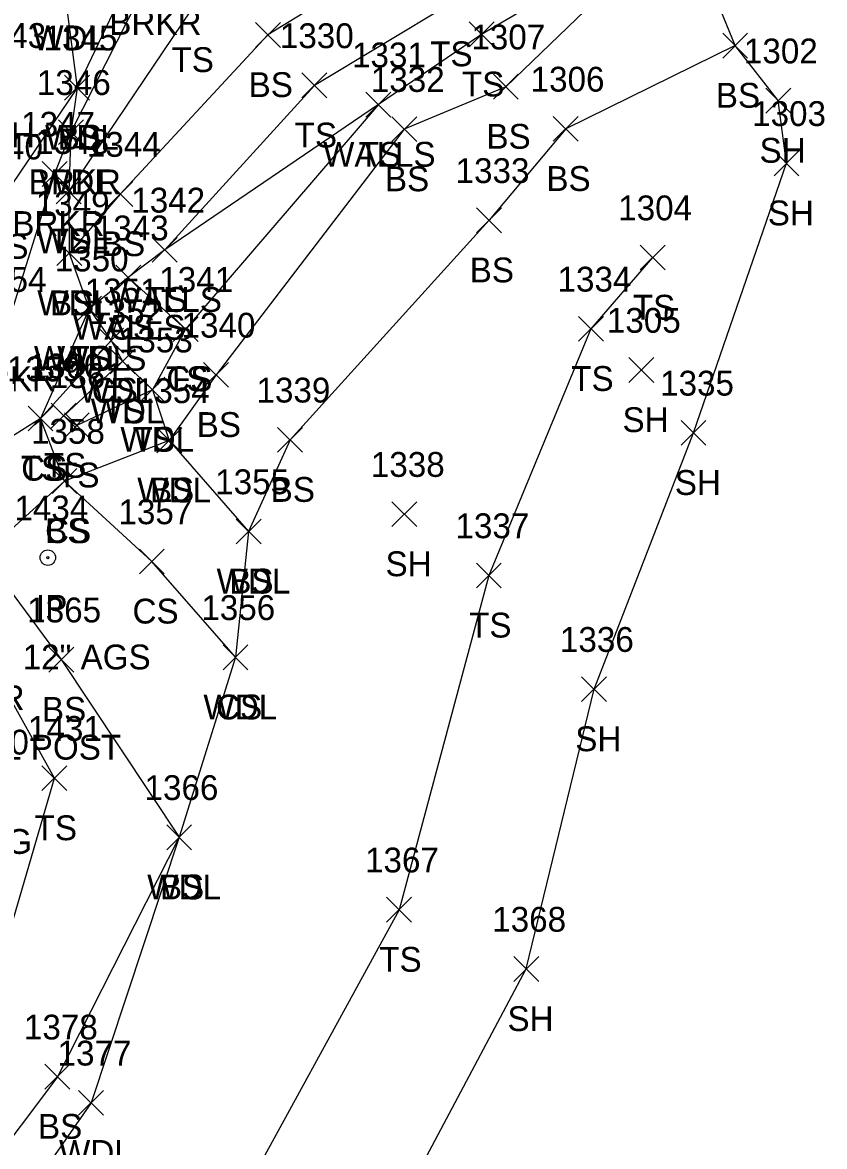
# Model space of a CAD drawing. Extents: x 1441651 to 1442140, y 243798 to 245625.
# Drawn here: x 1442075.5 to 1442140.1, y 245354.1 to 245444.6 of the extents above; entities that cross this region are included whole.
import ezdxf

# ---------------------------------------------------------------- set-up
doc = ezdxf.new("R2010")
doc.units = 0
for name, color, linetype in [('L_A', 7, 'Continuous'), ('L_I', 7, 'Continuous'), ('L_TIC', 7, 'Continuous'), ('LAWA', 7, 'Continuous'), ('LAWE', 7, 'Continuous'), ('LELB', 7, 'Continuous'), ('LSOGP', 7, 'Continuous'), ('LWS', 7, 'Continuous'), ('M_A', 7, 'Continuous'), ('M_C', 7, 'Continuous'), ('M_I', 7, 'Continuous'), ('MPIR', 7, 'Continuous'), ('P_A', 7, 'Continuous'), ('P_I', 7, 'Continuous'), ('R_A', 7, 'Continuous'), ('R_C', 7, 'Continuous')]:
    doc.layers.add(name, color=color, linetype=linetype)

msp = doc.modelspace()

# ---------------------------------------------------------------- linework, layer by layer
at = {"layer": 'L_TIC'}
for points in [[(1442094.312, 245442.627), (1442096.312, 245444.627)], [(1442096.312, 245442.627), (1442094.312, 245444.627)], [(1442111.528, 245442.672), (1442113.528, 245444.672)], [(1442113.528, 245442.672), (1442111.528, 245444.672)], [(1442131.95, 245441.769), (1442133.95, 245443.769)], [(1442133.95, 245441.769), (1442131.95, 245443.769)], [(1442098.053, 245438.565), (1442100.053, 245440.565)], [(1442100.053, 245438.565), (1442098.053, 245440.565)], [(1442078.931, 245438.38), (1442080.931, 245440.38)], [(1442080.931, 245438.38), (1442078.931, 245440.38)], [(1442078.931, 245438.38), (1442080.931, 245440.38)], [(1442080.931, 245438.38), (1442078.931, 245440.38)], [(1442113.47, 245438.461), (1442115.47, 245440.461)], [(1442115.47, 245438.461), (1442113.47, 245440.461)], [(1442103.209, 245437.017), (1442105.209, 245439.017)], [(1442105.209, 245437.017), (1442103.209, 245439.017)], [(1442103.209, 245437.017), (1442105.209, 245439.017)], [(1442105.209, 245437.017), (1442103.209, 245439.017)], [(1442135.427, 245437.337), (1442137.427, 245439.337)], [(1442137.427, 245437.337), (1442135.427, 245439.337)], [(1442105.293, 245435.041), (1442107.293, 245437.041)], [(1442107.293, 245435.041), (1442105.293, 245437.041)], [(1442118.3, 245435.064), (1442120.3, 245437.064)], [(1442120.3, 245435.064), (1442118.3, 245437.064)], [(1442078.446, 245434.792), (1442080.446, 245436.792)], [(1442080.446, 245434.792), (1442078.446, 245436.792)], [(1442078.446, 245434.792), (1442080.446, 245436.792)], [(1442080.446, 245434.792), (1442078.446, 245436.792)], [(1442136.088, 245432.293), (1442138.088, 245434.293)], [(1442138.088, 245432.293), (1442136.088, 245434.293)], [(1442077.126, 245431.436), (1442079.126, 245433.436)], [(1442079.126, 245431.436), (1442077.126, 245433.436)], [(1442078.259, 245430.039), (1442080.259, 245432.039)], [(1442080.259, 245430.039), (1442078.259, 245432.039)], [(1442078.259, 245430.039), (1442080.259, 245432.039)], [(1442080.259, 245430.039), (1442078.259, 245432.039)], [(1442082.416, 245429.813), (1442084.416, 245431.813)], [(1442084.416, 245429.813), (1442082.416, 245431.813)], [(1442112.122, 245427.701), (1442114.122, 245429.701)], [(1442114.122, 245427.701), (1442112.122, 245429.701)], [(1442078.309, 245425.048), (1442080.309, 245427.048)], [(1442080.309, 245425.048), (1442078.309, 245427.048)], [(1442078.309, 245425.048), (1442080.309, 245427.048)], [(1442080.309, 245425.048), (1442078.309, 245427.048)], [(1442085.997, 245425.322), (1442087.997, 245427.322)], [(1442087.997, 245425.322), (1442085.997, 245427.322)], [(1442085.997, 245425.322), (1442087.997, 245427.322)], [(1442087.997, 245425.322), (1442085.997, 245427.322)], [(1442125.299, 245424.698), (1442127.299, 245426.698)], [(1442127.299, 245424.698), (1442125.299, 245426.698)], [(1442083.06, 245423.085), (1442085.06, 245425.085)], [(1442085.06, 245423.085), (1442083.06, 245425.085)], [(1442083.06, 245423.085), (1442085.06, 245425.085)], [(1442085.06, 245423.085), (1442083.06, 245425.085)], [(1442079.914, 245420.582), (1442081.914, 245422.582)], [(1442081.914, 245420.582), (1442079.914, 245422.582)], [(1442079.914, 245420.582), (1442081.914, 245422.582)], [(1442081.914, 245420.582), (1442079.914, 245422.582)], [(1442079.914, 245420.582), (1442081.914, 245422.582)], [(1442081.914, 245420.582), (1442079.914, 245422.582)], [(1442087.683, 245418.936), (1442089.683, 245420.936)], [(1442089.683, 245418.936), (1442087.683, 245420.936)], [(1442087.683, 245418.936), (1442089.683, 245420.936)], [(1442089.683, 245418.936), (1442087.683, 245420.936)], [(1442120.335, 245418.958), (1442122.335, 245420.958)], [(1442122.335, 245418.958), (1442120.335, 245420.958)], [(1442081.678, 245418.008), (1442083.678, 245420.008)], [(1442083.678, 245418.008), (1442081.678, 245420.008)], [(1442081.678, 245418.008), (1442083.678, 245420.008)], [(1442083.678, 245418.008), (1442081.678, 245420.008)], [(1442082.608, 245416.345), (1442084.608, 245418.345)], [(1442084.608, 245416.345), (1442082.608, 245418.345)], [(1442082.608, 245416.345), (1442084.608, 245418.345)], [(1442084.608, 245416.345), (1442082.608, 245418.345)], [(1442090.133, 245415.249), (1442092.133, 245417.249)], [(1442092.133, 245415.249), (1442090.133, 245417.249)], [(1442124.388, 245415.642), (1442126.388, 245417.642)], [(1442126.388, 245415.642), (1442124.388, 245417.642)], [(1442084.999, 245414.059), (1442086.999, 245416.059)], [(1442086.999, 245414.059), (1442084.999, 245416.059)], [(1442084.999, 245414.059), (1442086.999, 245416.059)], [(1442086.999, 245414.059), (1442084.999, 245416.059)], [(1442075.992, 245411.732), (1442077.992, 245413.732)], [(1442077.992, 245411.732), (1442075.992, 245413.732)], [(1442075.992, 245411.732), (1442077.992, 245413.732)], [(1442077.992, 245411.732), (1442075.992, 245413.732)], [(1442075.992, 245411.732), (1442077.992, 245413.732)], [(1442077.992, 245411.732), (1442075.992, 245413.732)], [(1442077.858, 245411.961), (1442079.858, 245413.961)], [(1442079.858, 245411.961), (1442077.858, 245413.961)], [(1442078.917, 245411.184), (1442080.917, 245413.184)], [(1442080.917, 245411.184), (1442078.917, 245413.184)], [(1442078.917, 245411.184), (1442080.917, 245413.184)], [(1442080.917, 245411.184), (1442078.917, 245413.184)], [(1442128.596, 245410.581), (1442130.596, 245412.581)], [(1442130.596, 245410.581), (1442128.596, 245412.581)], [(1442086.362, 245409.975), (1442088.362, 245411.975)], [(1442088.362, 245409.975), (1442086.362, 245411.975)], [(1442086.362, 245409.975), (1442088.362, 245411.975)], [(1442088.362, 245409.975), (1442086.362, 245411.975)], [(1442096.091, 245410.023), (1442098.091, 245412.023)], [(1442098.091, 245410.023), (1442096.091, 245412.023)], [(1442077.918, 245406.703), (1442079.918, 245408.703)], [(1442079.918, 245406.703), (1442077.918, 245408.703)], [(1442077.918, 245406.703), (1442079.918, 245408.703)], [(1442079.918, 245406.703), (1442077.918, 245408.703)], [(1442105.295, 245404.036), (1442107.295, 245406.036)], [(1442107.295, 245404.036), (1442105.295, 245406.036)], [(1442092.756, 245402.639), (1442094.756, 245404.639)], [(1442094.756, 245402.639), (1442092.756, 245404.639)], [(1442092.756, 245402.639), (1442094.756, 245404.639)], [(1442094.756, 245402.639), (1442092.756, 245404.639)], [(1442084.96, 245400.224), (1442086.96, 245402.224)], [(1442086.96, 245400.224), (1442084.96, 245402.224)], [(1442112.11, 245399.096), (1442114.11, 245401.096)], [(1442114.11, 245399.096), (1442112.11, 245401.096)], [(1442091.693, 245392.503), (1442093.693, 245394.503)], [(1442093.693, 245392.503), (1442091.693, 245394.503)], [(1442091.693, 245392.503), (1442093.693, 245394.503)], [(1442093.693, 245392.503), (1442091.693, 245394.503)], [(1442077.662, 245392.315), (1442079.662, 245394.315)], [(1442079.662, 245392.315), (1442077.662, 245394.315)], [(1442120.582, 245389.94), (1442122.582, 245391.94)], [(1442122.582, 245389.94), (1442120.582, 245391.94)], [(1442077.106, 245382.773), (1442079.106, 245384.773)], [(1442079.106, 245382.773), (1442077.106, 245384.773)], [(1442087.165, 245378.007), (1442089.165, 245380.007)], [(1442089.165, 245378.007), (1442087.165, 245380.007)], [(1442087.165, 245378.007), (1442089.165, 245380.007)], [(1442089.165, 245378.007), (1442087.165, 245380.007)], [(1442104.872, 245372.176), (1442106.872, 245374.176)], [(1442106.872, 245372.176), (1442104.872, 245374.176)], [(1442115.121, 245367.402), (1442117.121, 245369.402)], [(1442117.121, 245367.402), (1442115.121, 245369.402)], [(1442077.347, 245358.722), (1442079.347, 245360.722)], [(1442079.347, 245358.722), (1442077.347, 245360.722)], [(1442080.06, 245356.624), (1442082.06, 245358.624)], [(1442082.06, 245356.624), (1442080.06, 245358.624)]]:
    msp.add_lwpolyline(points, dxfattribs=at)
at = {"layer": 'LAWA'}
msp.add_lwpolyline([(1442094.004, 245495.984), (1442085.8, 245486.892), (1442079.595, 245477.001), (1442071.155, 245464.784), (1442068.683, 245457.119), (1442071.044, 245454.669), (1442072.716, 245452.8), (1442077.346, 245452.135), (1442078.907, 245447.391), (1442079.931, 245439.38), (1442079.446, 245435.792), (1442079.259, 245431.039), (1442079.309, 245426.048), (1442080.914, 245421.582), (1442082.678, 245419.008), (1442083.608, 245417.345), (1442085.999, 245415.059), (1442087.362, 245410.975), (1442093.756, 245403.639), (1442092.693, 245393.503), (1442088.165, 245379.007), (1442081.06, 245357.624), (1442070.182, 245342.029)], dxfattribs=at)
at = {"layer": 'LAWE'}
msp.add_lwpolyline([(1442108.799, 245476.467), (1442096.827, 245461.697), (1442085.936, 245448.636), (1442079.446, 245435.792), (1442078.126, 245432.436), (1442074.215, 245419.929), (1442069.905, 245412.33), (1442066.174, 245406.441), (1442060.085, 245400.813), (1442053.875, 245394.968), (1442048.801, 245389.024), (1442033.753, 245369.5), (1442027.295, 245353.918), (1442016.143, 245332.931), (1442008.363, 245317.18), (1442000.261, 245295.499)], dxfattribs=at)
at = {"layer": 'LELB'}
for points in [[(1442107.479, 245478.045), (1442095.111, 245463.136), (1442085.124, 245450.231), (1442079.931, 245439.38), (1442074.016, 245430.6), (1442072.192, 245422.421), (1442067.602, 245415.77), (1442063.525, 245410.875), (1442058.938, 245403.451), (1442051.468, 245396.66), (1442047.361, 245390.552), (1442031.625, 245371.637), (1442024.894, 245355.937), (1442013.328, 245334.791), (1442005.478, 245318.663), (1441997.832, 245296.612)], [(1442110.371, 245473.904), (1442098.105, 245459.473), (1442089.13, 245445.639), (1442079.259, 245431.039)], [(1442122.519, 245456.753), (1442106.231, 245450.329), (1442095.312, 245443.627), (1442083.416, 245430.813), (1442079.309, 245426.048)], [(1442128.7, 245453.168), (1442114.47, 245439.461), (1442106.293, 245436.041), (1442091.133, 245416.249), (1442087.362, 245410.975), (1442078.918, 245407.703), (1442072.375, 245401.791), (1442078.662, 245393.315), (1442088.165, 245379.007), (1442078.347, 245359.722), (1442066.466, 245343.929), (1442051.618, 245313.899)], [(1442128.7, 245453.168), (1442112.528, 245443.672), (1442104.209, 245438.017), (1442088.683, 245419.936), (1442085.999, 245415.059), (1442079.917, 245412.184)], [(1442128.7, 245453.168), (1442109.973, 245446.107), (1442099.053, 245439.565), (1442086.997, 245426.322)], [(1442132.95, 245442.769), (1442119.3, 245436.064), (1442113.122, 245428.701), (1442097.091, 245411.023), (1442093.756, 245403.639)], [(1442126.299, 245425.698), (1442121.335, 245419.958), (1442113.11, 245400.096), (1442105.872, 245373.176), (1442091.625, 245347.116), (1442084.744, 245336.784), (1442070.953, 245307.446)], [(1442088.683, 245419.936), (1442084.06, 245424.085), (1442082.678, 245419.008), (1442076.992, 245412.732)], [(1442080.914, 245421.582), (1442076.992, 245412.732), (1442069.82, 245408.225)], [(1442083.608, 245417.345), (1442078.858, 245412.961), (1442079.917, 245412.184)], [(1442092.693, 245393.503), (1442085.96, 245401.224), (1442078.918, 245407.703), (1442076.992, 245412.732)], [(1442066.466, 245343.929), (1442078.106, 245383.773), (1442072.276, 245394.261)]]:
    msp.add_lwpolyline(points, dxfattribs=at)
at = {"layer": 'LSOGP'}
msp.add_lwpolyline([(1442101.45, 245340.824), (1442116.121, 245368.402), (1442121.582, 245390.94), (1442129.596, 245411.581), (1442137.088, 245433.293), (1442136.427, 245438.337), (1442132.95, 245442.769), (1442128.7, 245453.168), (1442122.519, 245456.753), (1442110.371, 245473.904), (1442108.799, 245476.467), (1442107.479, 245478.045), (1442106.124, 245480.602), (1442104.092, 245484.162), (1442102.458, 245487.565), (1442099.331, 245492.7), (1442094.004, 245495.984), (1442092.912, 245497.466), (1442087.101, 245508.937)], dxfattribs=at)
at = {"layer": 'LWS'}
msp.add_lwpolyline([(1442104.209, 245438.017), (1442086.997, 245426.322), (1442084.06, 245424.085), (1442080.914, 245421.582)], dxfattribs=at)
at = {"layer": 'MPIR'}
for radius in [0.625, 0.0833]:
    msp.add_circle((1442077.58, 245401.531), radius, dxfattribs=at)

# ---------------------------------------------------------------- texts
at = {"layer": 'L_A'}
for s, p in [('BRKR', (1442082.527, 245443.636)), ('WDL', (1442076.325, 245442.391)), ('TS', (1442087.539, 245440.639)), ('TS', (1442108.382, 245441.107)), ('BS', (1442093.753, 245438.627)), ('TS', (1442110.937, 245438.672)), ('BS', (1442131.391, 245437.769)), ('CH', (1442072.676, 245434.58)), ('WDL', (1442077.349, 245434.38)), ('BS', (1442078.372, 245434.38)), ('TS', (1442097.462, 245434.565)), ('BS', (1442112.911, 245434.461)), ('SH', (1442134.915, 245433.337)), ('WALLS', (1442099.752, 245433.017)), ('TS', (1442102.619, 245433.017)), ('BRKR', (1442076.036, 245430.792)), ('WDL', (1442076.863, 245430.792)), ('BS', (1442104.734, 245431.041)), ('BS', (1442117.741, 245431.064)), ('SH', (1442135.576, 245428.293)), ('BRKR', (1442074.717, 245427.436)), ('WDL', (1442076.676, 245426.039)), ('TS', (1442077.668, 245426.039)), ('BS', (1442081.857, 245425.813)), ('BS', (1442072.457, 245425.6)), ('BS', (1442111.563, 245423.701)), ('WALLS', (1442082.54, 245421.322)), ('TS', (1442085.406, 245421.322)), ('WDL', (1442076.727, 245421.048)), ('BS', (1442077.75, 245421.048)), ('TS', (1442124.709, 245420.698)), ('WALLS', (1442079.603, 245419.085)), ('CS', (1442082.501, 245419.085)), ('WALLS', (1442076.457, 245416.582)), ('WDL', (1442078.331, 245416.582)), ('TS', (1442079.324, 245416.582)), ('TS', (1442087.092, 245414.936)), ('CS', (1442087.124, 245414.936)), ('TS', (1442119.745, 245414.958)), ('BRKR', (1442070.806, 245414.929)), ('WDL', (1442080.095, 245414.008)), ('CS', (1442081.119, 245414.008)), ('WDL', (1442081.025, 245412.345)), ('TS', (1442082.017, 245412.345)), ('SH', (1442123.876, 245411.642)), ('BS', (1442089.574, 245411.249)), ('WDL', (1442083.416, 245410.059)), ('TS', (1442084.408, 245410.059)), ('TS', (1442075.402, 245407.732)), ('CS', (1442075.433, 245407.732)), ('CS', (1442075.433, 245407.732)), ('TS', (1442077.267, 245407.961)), ('TS', (1442078.326, 245407.184)), ('TS', (1442078.326, 245407.184)), ('WDL', (1442084.78, 245405.975)), ('BS', (1442085.803, 245405.975)), ('BS', (1442095.532, 245406.023)), ('SH', (1442128.084, 245406.581)), ('CS', (1442077.359, 245402.703)), ('BS', (1442077.359, 245402.703)), ('SH', (1442104.783, 245400.036)), ('WDL', (1442091.174, 245398.639)), ('BS', (1442092.197, 245398.639)), ('CS', (1442084.401, 245396.224)), ('TS', (1442111.519, 245395.096)), ('BS', (1442077.103, 245388.315)), ('WDL', (1442090.111, 245388.503)), ('CS', (1442091.134, 245388.503)), ('SH', (1442120.07, 245385.94)), ('TS', (1442076.516, 245378.773)), ('WDL', (1442085.583, 245374.007)), ('BS', (1442086.606, 245374.007)), ('TS', (1442104.281, 245368.176)), ('SH', (1442114.609, 245363.402)), ('BS', (1442076.788, 245354.722)), ('WDL', (1442078.477, 245352.624))]:
    msp.add_text(s, height=2, dxfattribs=at).set_placement(p)
at = {"layer": 'L_I'}
for s, p in [('1443', (1442071.495, 245442.58)), ('1345', (1442077.238, 245442.38)), ('1345', (1442077.238, 245442.38)), ('1330', (1442096.274, 245442.565)), ('1307', (1442111.699, 245442.461)), ('1302', (1442133.655, 245441.337)), ('1331', (1442102.083, 245441.017)), ('1331', (1442102.083, 245441.017)), ('1346', (1442076.698, 245438.792)), ('1346', (1442076.698, 245438.792)), ('1332', (1442103.6, 245439.041)), ('1306', (1442116.473, 245439.064)), ('1303', (1442134.316, 245436.293)), ('1347', (1442075.433, 245435.436)), ('1348', (1442076.566, 245434.039)), ('1348', (1442076.566, 245434.039)), ('1440', (1442071.236, 245433.6)), ('1344', (1442080.723, 245433.813)), ('1333', (1442110.429, 245431.701)), ('1349', (1442076.608, 245429.048)), ('1349', (1442076.608, 245429.048)), ('1342', (1442084.304, 245429.322)), ('1342', (1442084.304, 245429.322)), ('1304', (1442123.528, 245428.698)), ('1343', (1442081.367, 245427.085)), ('1343', (1442081.367, 245427.085)), ('1350', (1442078.135, 245424.582)), ('1350', (1442078.135, 245424.582)), ('1350', (1442078.135, 245424.582)), ('1454', (1442071.522, 245422.929)), ('1341', (1442086.557, 245422.936)), ('1341', (1442086.557, 245422.936)), ('1334', (1442118.642, 245422.958)), ('1351', (1442080.552, 245422.008)), ('1351', (1442080.552, 245422.008)), ('1352', (1442080.915, 245420.345)), ('1352', (1442080.915, 245420.345)), ('1305', (1442122.616, 245419.642)), ('1340', (1442088.354, 245419.249)), ('1353', (1442083.306, 245418.059)), ('1353', (1442083.306, 245418.059)), ('1360', (1442076.031, 245415.961)), ('1359', (1442074.291, 245415.732)), ('1359', (1442074.291, 245415.732)), ('1359', (1442074.291, 245415.732)), ('1361', (1442077.743, 245415.184)), ('1361', (1442077.743, 245415.184)), ('1335', (1442126.903, 245414.581)), ('1354', (1442084.67, 245413.975)), ('1354', (1442084.67, 245413.975)), ('1339', (1442094.39, 245414.023)), ('1358', (1442076.225, 245410.703)), ('1358', (1442076.225, 245410.703)), ('1338', (1442103.602, 245408.036)), ('1355', (1442091.063, 245406.639)), ('1355', (1442091.063, 245406.639)), ('1357', (1442083.267, 245404.224)), ('1337', (1442110.417, 245403.096)), ('1365', (1442075.922, 245396.315)), ('1356', (1442089.945, 245396.503)), ('1356', (1442089.945, 245396.503)), ('1336', (1442118.834, 245393.94)), ('1431', (1442075.98, 245386.773)), ('1366', (1442085.37, 245382.007)), ('1366', (1442085.37, 245382.007)), ('1367', (1442103.132, 245376.176)), ('1368', (1442113.38, 245371.402)), ('1378', (1442075.654, 245362.722)), ('1377', (1442078.367, 245360.624))]:
    msp.add_text(s, height=2, dxfattribs=at).set_placement(p)
at = {"layer": 'M_A'}
msp.add_text('IP', height=2, dxfattribs=at).set_placement((1442076.627, 245396.531))
at = {"layer": 'M_C'}
msp.add_text('3/8" IP 12" AGS', height=2, dxfattribs=at).set_placement((1442066.872, 245392.531))
at = {"layer": 'M_I'}
msp.add_text('1434', height=2, dxfattribs=at).set_placement((1442074.887, 245404.531))
at = {"layer": 'P_A'}
msp.add_text('RDG', height=2, dxfattribs=at).set_placement((1442070.369, 245377.672))
at = {"layer": 'P_I'}
msp.add_text('1430', height=2, dxfattribs=at).set_placement((1442070.102, 245385.672))
at = {"layer": 'R_A'}
msp.add_text('GRR', height=2, dxfattribs=at).set_placement((1442069.764, 245389.261))
at = {"layer": 'R_C'}
msp.add_text('SGR W/ STEEL POST', height=2, dxfattribs=at).set_placement((1442056.441, 245385.261))

doc.saveas('drawing.dxf')
